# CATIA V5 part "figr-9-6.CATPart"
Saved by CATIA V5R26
Part number: Part2
Bounding box of the stored display mesh (mm): x -75 to 75, y -75 to 96.278, z -26.878 to 0
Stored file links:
  D:\_Deepak\CATIA\CATIA V5-6R2016_Deepak\Resources\Part files\Partfiles\c09_catia_v5_6r2016_prt\figr-9-6.CATPart
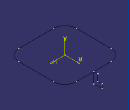
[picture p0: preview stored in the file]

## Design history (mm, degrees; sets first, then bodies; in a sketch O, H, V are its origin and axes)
Body1 (main body)
  Sketch1 on xy-plane, origin (0, 0, 0), H (1, 0, 0), V (0, 1, 0)
    point P1 (-75, 75)
    line L1 (-45, 75) -> (45, 75)
    line L2 (75, 45) -> (75, -45)
    line L3 (45, -75) -> (-45, -75)
    line L4 (-75, -45) -> (-75, 45)
    point P2 (75, 75)
    point P3 (75, -75)
    point P4 (-75, -75)
    axis line L5 (75, -75) -> (-75, 75)
    arc A1 centre (45, -45) radius 30 from (75, -45) to (45, -75) cw
    arc A2 centre (45, 45) radius 30 from (45, 75) to (75, 45) cw
    arc A3 centre (-45, 45) radius 30 from (-45, 75) to (-75, 45) ccw
    arc A4 centre (-45, -45) radius 30 from (-45, -75) to (-75, -45) cw
    distance P2 P3 = 150
    distance P3 P4 = 150
    radius A1 = 30
    radius A2 = 30
    radius A3 = 30
    radius A4 = 30
    horizontal: L1 H, L3 H
    vertical: L2 V, L4 V
    midpoint: O L5
    coincidence: L2 P3, L3 P3, L1 P2, L2 P2, L1 P1, L4 P1, L3 P4, L4 P4
    tangency: A1 L2, A1 L3, A2 L1, A2 L2, A3 L1, A3 L4, A4 L3, A4 L4
  Sketch2 on yz-plane, origin (0, 0, 0), H (0, 1, 0), V (0, 0, 1)
    point P1 (85, 0)
    line L1 (85, 0) -> (85, -16.8782)
    line L2 (85, -16.8782) -> (96.2781, -16.8782)
    line L3 (96.2781, -16.8782) -> (96.2781, -26.8782)
    line L4 (96.2781, -26.8782) -> (75, -26.8782)
    line L5 (75, -26.8782) -> (75, 0)
    point P6 (75, 0)
    line L6 (75, 0) -> (85, 0)
    reference projected point E1 (75, 0) from edge of Sketch1
    length L3 = 10
    length L6 = 10
    coincidence: P1 H, P6 H, P6 E1
    vertical: L1 V, L3 V, L5 V
    horizontal: L2 H, L4 H, L6 H
  Rib1: profile Sketch2, centre curve Sketch1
